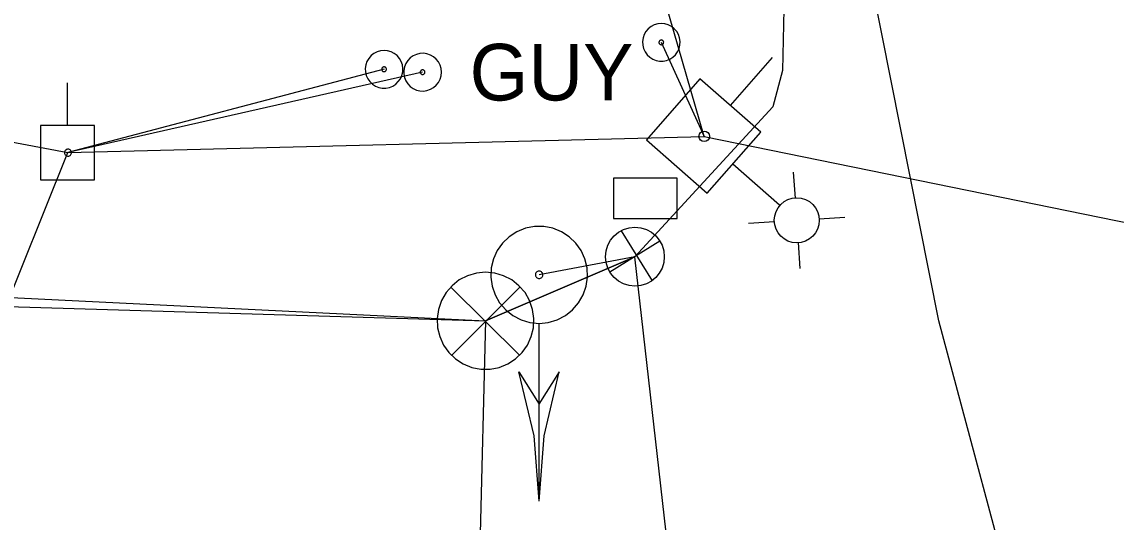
# Model space of a CAD drawing. Extents: x 596028 to 606371, y 330010 to 403088.
# Drawn here: x 604637.5 to 604712, y 339404.5 to 339438.6 of the extents above; entities that cross this region are included whole.
import ezdxf

# ---------------------------------------------------------------- set-up
doc = ezdxf.new("R2010")
doc.units = 0
for name, color, linetype in [('E_LTG', 7, 'Continuous'), ('E_SIG', 7, 'Continuous'), ('E_SIG_Conduit', 7, 'Continuous'), ('E_UTL_EGuyWire', 7, 'Continuous'), ('E_UTL_EPowerPole', 7, 'Continuous'), ('E_UTL_FO_MH', 7, 'Continuous'), ('E_UTL_FO_UG', 7, 'Continuous'), ('E_UTL_G_UG', 7, 'Continuous'), ('E_UTL_Loop_UG', 7, 'Continuous'), ('E_UTL_Overhead', 7, 'Continuous')]:
    doc.layers.add(name, color=color, linetype=linetype)

# ---------------------------------------------------------------- blocks, each defined once
blk = doc.blocks.new('_U333')
at = {"layer": 'E_SIG'}
for p, q in [((0, 6.1), (0, -6.1)), ((-6.09, 0.4), (6.1, 0.4))]:
    blk.add_line(p, q, dxfattribs=at)
blk.add_circle((0, 0.01), 6.1, dxfattribs=at)
blk = doc.blocks.new('PPLM')
at = {"layer": 'E_LTG'}
for p, q in [((37.76, 4.8), (31.39, 11.15)), ((48.66, 4.8), (55.01, 11.15)), ((35.29, -0.66), (13.76, -0.66)), ((37.76, -6.1), (31.39, -12.47)), ((48.66, -6.1), (55.01, -12.47))]:
    blk.add_line(p, q, dxfattribs=at)
blk.add_circle((43.2, -0.66), 7.79, dxfattribs=at)
at = {"layer": 'E_UTL_EPowerPole'}
blk.add_line((-0.24, 14), (-0.24, 36.1), dxfattribs=at)
blk.add_lwpolyline([(-14.25, -14.05), (13.76, -14.05), (13.76, 14), (-14.25, 14)], close=True, dxfattribs=at)
blk.add_circle((0, 0), 1.81, dxfattribs=at)

msp = doc.modelspace()

# ---------------------------------------------------------------- linework, layer by layer
at = {"layer": 'E_SIG'}
for points in [[(604672.74, 339418.06), (604673.365, 339418.12), (604673.967, 339418.297), (604674.524, 339418.584), (604675.017, 339418.972), (604675.428, 339419.446), (604675.742, 339419.989), (604675.947, 339420.582), (604676.036, 339421.203), (604676.007, 339421.83), (604675.859, 339422.44), (604675.598, 339423.01), (604675.234, 339423.521), (604674.78, 339423.954), (604674.252, 339424.294), (604673.67, 339424.527), (604673.054, 339424.645), (604672.426, 339424.645), (604671.81, 339424.527), (604671.228, 339424.294), (604670.7, 339423.954), (604670.246, 339423.521), (604669.882, 339423.01), (604669.622, 339422.44), (604669.474, 339421.83), (604669.444, 339421.203), (604669.533, 339420.582), (604669.738, 339419.989), (604670.052, 339419.446), (604670.463, 339418.972), (604670.956, 339418.584), (604671.514, 339418.297), (604672.116, 339418.12), (604672.74, 339418.06)], [(604669.09, 339421.533), (604668.465, 339421.473), (604667.863, 339421.296), (604667.305, 339421.009), (604666.812, 339420.621), (604666.401, 339420.147), (604666.088, 339419.604), (604665.883, 339419.011), (604665.793, 339418.39), (604665.823, 339417.763), (604665.971, 339417.154), (604666.232, 339416.583), (604666.596, 339416.072), (604667.05, 339415.639), (604667.577, 339415.3), (604668.16, 339415.067), (604668.776, 339414.948), (604669.403, 339414.948), (604670.019, 339415.067), (604670.602, 339415.3), (604671.129, 339415.639), (604671.583, 339416.072), (604671.947, 339416.583), (604672.208, 339417.154), (604672.356, 339417.763), (604672.386, 339418.39), (604672.296, 339419.011), (604672.091, 339419.604), (604671.778, 339420.147), (604671.367, 339420.621), (604670.874, 339421.009), (604670.316, 339421.296), (604669.714, 339421.473), (604669.09, 339421.533)], [(604672.74, 339421.108), (604672.788, 339421.113), (604672.834, 339421.126), (604672.877, 339421.148), (604672.914, 339421.178), (604672.946, 339421.214), (604672.97, 339421.256), (604672.985, 339421.301), (604672.992, 339421.348), (604672.99, 339421.396), (604672.979, 339421.443), (604672.959, 339421.487), (604672.931, 339421.526), (604672.896, 339421.559), (604672.856, 339421.585), (604672.811, 339421.603), (604672.764, 339421.612), (604672.716, 339421.612), (604672.669, 339421.603), (604672.624, 339421.585), (604672.584, 339421.559), (604672.549, 339421.526), (604672.522, 339421.487), (604672.502, 339421.443), (604672.49, 339421.396), (604672.488, 339421.348), (604672.495, 339421.301), (604672.511, 339421.256), (604672.535, 339421.214), (604672.566, 339421.178), (604672.604, 339421.148), (604672.646, 339421.126), (604672.692, 339421.113), (604672.74, 339421.108)], [(604666.755, 339420.495), (604671.412, 339415.885)], [(604666.803, 339415.885), (604671.455, 339420.538)], [(604672.739, 339405.961), (604672.739, 339418.002)], [(604672.74, 339405.96), (604672.394, 339410.414), (604671.365, 339414.76)], [(604671.367, 339414.76), (604672.739, 339412.56)], [(604672.739, 339412.56), (604674.116, 339414.76)], [(604672.74, 339405.96), (604673.086, 339410.414), (604674.115, 339414.76)]]:
    msp.add_lwpolyline(points, dxfattribs=at)
at = {"layer": 'E_SIG_Conduit'}
msp.add_line((604534.037, 339424.821), (604669.091, 339418.231), dxfattribs=at)
for points in [[(604685.541, 339453.141), (604685.981, 339451.881), (604688.351, 339445.561), (604689.391, 339439.431), (604689.301, 339435.251), (604688.651, 339432.791)], [(604688.651, 339432.791), (604679.261, 339422.591)], [(604679.261, 339422.591), (604669.091, 339418.231)], [(604679.261, 339422.591), (604672.741, 339421.361)], [(604707.661, 339319.651), (604684.561, 339375.861), (604679.261, 339422.591)]]:
    msp.add_lwpolyline(points, dxfattribs=at)
at = {"layer": 'E_UTL_EGuyWire'}
for p, q in [((604683.979, 339430.78), (604681.327, 339439.949)), ((604681.06, 339437.176), (604683.979, 339430.78)), ((604662.18, 339435.343), (604640.658, 339429.671)), ((604664.8, 339435.146), (604640.658, 339429.671))]:
    msp.add_line(p, q, dxfattribs=at)
for points in [[(604681.06, 339438.459), (604680.817, 339438.436), (604680.583, 339438.367), (604680.366, 339438.256), (604680.174, 339438.105), (604680.015, 339437.92), (604679.893, 339437.709), (604679.813, 339437.479), (604679.778, 339437.237), (604679.79, 339436.993), (604679.847, 339436.756), (604679.949, 339436.534), (604680.09, 339436.336), (604680.267, 339436.167), (604680.472, 339436.035), (604680.698, 339435.945), (604680.938, 339435.898), (604681.182, 339435.898), (604681.422, 339435.945), (604681.648, 339436.035), (604681.853, 339436.167), (604682.03, 339436.336), (604682.171, 339436.534), (604682.273, 339436.756), (604682.33, 339436.993), (604682.342, 339437.237), (604682.307, 339437.479), (604682.227, 339437.709), (604682.105, 339437.92), (604681.946, 339438.105), (604681.754, 339438.256), (604681.537, 339438.367), (604681.303, 339438.436), (604681.06, 339438.459)], [(604681.06, 339437.336), (604681.03, 339437.334), (604681, 339437.325), (604680.973, 339437.311), (604680.949, 339437.292), (604680.929, 339437.269), (604680.914, 339437.243), (604680.904, 339437.214), (604680.9, 339437.184), (604680.901, 339437.153), (604680.908, 339437.124), (604680.921, 339437.096), (604680.939, 339437.071), (604680.961, 339437.05), (604680.986, 339437.033), (604681.015, 339437.022), (604681.045, 339437.016), (604681.075, 339437.016), (604681.105, 339437.022), (604681.134, 339437.033), (604681.159, 339437.05), (604681.181, 339437.071), (604681.199, 339437.096), (604681.212, 339437.124), (604681.219, 339437.153), (604681.22, 339437.184), (604681.216, 339437.214), (604681.206, 339437.243), (604681.191, 339437.269), (604681.171, 339437.292), (604681.147, 339437.311), (604681.12, 339437.325), (604681.09, 339437.334), (604681.06, 339437.336)], [(604662.18, 339436.626), (604661.937, 339436.603), (604661.703, 339436.534), (604661.486, 339436.423), (604661.294, 339436.272), (604661.135, 339436.087), (604661.013, 339435.876), (604660.933, 339435.646), (604660.898, 339435.404), (604660.91, 339435.16), (604660.967, 339434.923), (604661.069, 339434.701), (604661.21, 339434.503), (604661.387, 339434.334), (604661.592, 339434.202), (604661.818, 339434.112), (604662.058, 339434.065), (604662.302, 339434.065), (604662.542, 339434.112), (604662.768, 339434.202), (604662.973, 339434.334), (604663.15, 339434.503), (604663.291, 339434.701), (604663.393, 339434.923), (604663.45, 339435.16), (604663.462, 339435.404), (604663.427, 339435.646), (604663.347, 339435.876), (604663.225, 339436.087), (604663.066, 339436.272), (604662.874, 339436.423), (604662.657, 339436.534), (604662.423, 339436.603), (604662.18, 339436.626)], [(604666.083, 339435.146), (604666.06, 339435.389), (604665.991, 339435.623), (604665.88, 339435.84), (604665.729, 339436.032), (604665.544, 339436.191), (604665.333, 339436.313), (604665.103, 339436.393), (604664.861, 339436.428), (604664.617, 339436.416), (604664.38, 339436.359), (604664.158, 339436.257), (604663.96, 339436.116), (604663.791, 339435.939), (604663.659, 339435.734), (604663.569, 339435.508), (604663.522, 339435.268), (604663.522, 339435.024), (604663.569, 339434.784), (604663.659, 339434.558), (604663.791, 339434.353), (604663.96, 339434.176), (604664.158, 339434.035), (604664.38, 339433.933), (604664.617, 339433.876), (604664.861, 339433.864), (604665.103, 339433.899), (604665.333, 339433.979), (604665.544, 339434.101), (604665.729, 339434.26), (604665.88, 339434.452), (604665.991, 339434.669), (604666.06, 339434.903), (604666.083, 339435.146)], [(604662.18, 339435.503), (604662.15, 339435.501), (604662.12, 339435.492), (604662.093, 339435.478), (604662.069, 339435.459), (604662.049, 339435.436), (604662.034, 339435.41), (604662.024, 339435.381), (604662.02, 339435.351), (604662.021, 339435.32), (604662.028, 339435.291), (604662.041, 339435.263), (604662.059, 339435.238), (604662.081, 339435.217), (604662.106, 339435.2), (604662.135, 339435.189), (604662.165, 339435.183), (604662.195, 339435.183), (604662.225, 339435.189), (604662.254, 339435.2), (604662.279, 339435.217), (604662.301, 339435.238), (604662.319, 339435.263), (604662.332, 339435.291), (604662.339, 339435.32), (604662.34, 339435.351), (604662.336, 339435.381), (604662.326, 339435.41), (604662.311, 339435.436), (604662.291, 339435.459), (604662.267, 339435.478), (604662.24, 339435.492), (604662.21, 339435.501), (604662.18, 339435.503)], [(604664.96, 339435.146), (604664.958, 339435.176), (604664.949, 339435.206), (604664.935, 339435.233), (604664.916, 339435.257), (604664.893, 339435.277), (604664.867, 339435.292), (604664.838, 339435.302), (604664.808, 339435.306), (604664.777, 339435.305), (604664.748, 339435.298), (604664.72, 339435.285), (604664.695, 339435.267), (604664.674, 339435.245), (604664.657, 339435.22), (604664.646, 339435.191), (604664.64, 339435.161), (604664.64, 339435.131), (604664.646, 339435.101), (604664.657, 339435.072), (604664.674, 339435.047), (604664.695, 339435.025), (604664.72, 339435.007), (604664.748, 339434.994), (604664.777, 339434.987), (604664.808, 339434.986), (604664.838, 339434.99), (604664.867, 339435), (604664.893, 339435.015), (604664.916, 339435.035), (604664.935, 339435.059), (604664.949, 339435.086), (604664.958, 339435.116), (604664.96, 339435.146)]]:
    msp.add_lwpolyline(points, dxfattribs=at)
at = {"layer": 'E_UTL_EPowerPole'}
for points in [[(604640.626, 339431.514), (604640.626, 339434.422)], [(604642.47, 339431.514), (604638.782, 339431.514)], [(604638.782, 339431.514), (604638.782, 339427.822)], [(604642.47, 339427.822), (604642.47, 339431.514)], [(604640.896, 339429.671), (604640.892, 339429.716), (604640.879, 339429.76), (604640.859, 339429.8), (604640.831, 339429.836), (604640.796, 339429.865), (604640.757, 339429.888), (604640.714, 339429.903), (604640.669, 339429.909), (604640.624, 339429.907), (604640.58, 339429.896), (604640.539, 339429.878), (604640.502, 339429.851), (604640.471, 339429.818), (604640.446, 339429.78), (604640.429, 339429.738), (604640.421, 339429.694), (604640.421, 339429.648), (604640.429, 339429.604), (604640.446, 339429.562), (604640.471, 339429.524), (604640.502, 339429.491), (604640.539, 339429.464), (604640.58, 339429.446), (604640.624, 339429.435), (604640.669, 339429.433), (604640.714, 339429.439), (604640.757, 339429.454), (604640.796, 339429.477), (604640.831, 339429.506), (604640.859, 339429.542), (604640.879, 339429.582), (604640.892, 339429.626), (604640.896, 339429.671)], [(604638.782, 339427.822), (604642.47, 339427.822)]]:
    msp.add_lwpolyline(points, dxfattribs=at)
at = {"layer": 'E_UTL_FO_MH'}
msp.add_lwpolyline([(604682.139, 339427.94), (604677.806, 339427.94), (604677.806, 339425.19), (604682.139, 339425.19)], close=True, dxfattribs=at)
at = {"layer": 'E_UTL_FO_UG'}
msp.add_lwpolyline([(604540.375, 339422.08), (604669.091, 339418.231), (604679.261, 339422.591)], dxfattribs=at)
at = {"layer": 'E_UTL_G_UG'}
msp.add_lwpolyline([(604742.351, 339228.682), (604740.051, 339238.172), (604732.171, 339281.151), (604723.131, 339319.311), (604718.151, 339342.271), (604709.951, 339377.231), (604705.891, 339396.141), (604699.951, 339418.231), (604694.751, 339444.391), (604689.121, 339468.851), (604685.031, 339486.701), (604684.681, 339487.291), (604678.371, 339490.441), (604676.201, 339500.021)], dxfattribs=at)
at = {"layer": 'E_UTL_Loop_UG'}
msp.add_line((604669.091, 339418.231), (604668.606, 339398.668), dxfattribs=at)
at = {"layer": 'E_UTL_Overhead'}
msp.add_line((604593.894, 339313.753), (604640.658, 339429.671), dxfattribs=at)
msp.add_lwpolyline([(604487.168, 339458.603), (604640.658, 339429.671), (604683.979, 339430.78), (604818.922, 339403.26), (604974.133, 339363.63), (605153.062, 339361.475)], dxfattribs=at)

# ---------------------------------------------------------------- block references
at = {"layer": 'E_SIG_Conduit', "xscale": 0.32808333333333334, "yscale": 0.32808333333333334, "rotation": -58.10434396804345}
msp.add_blockref('_U333', (604679.261, 339422.591), dxfattribs=at)
at = {"layer": 'E_UTL_EPowerPole', "xscale": 0.19684999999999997, "yscale": 0.19685, "rotation": -41.298203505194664}
msp.add_blockref('PPLM', (604683.979, 339430.78), dxfattribs=at)

# ---------------------------------------------------------------- texts
at = {"layer": 'E_UTL_EGuyWire'}
msp.add_text('GUY', height=3.85, dxfattribs=at).set_placement((604668.008, 339433.221))

doc.saveas('drawing.dxf')
